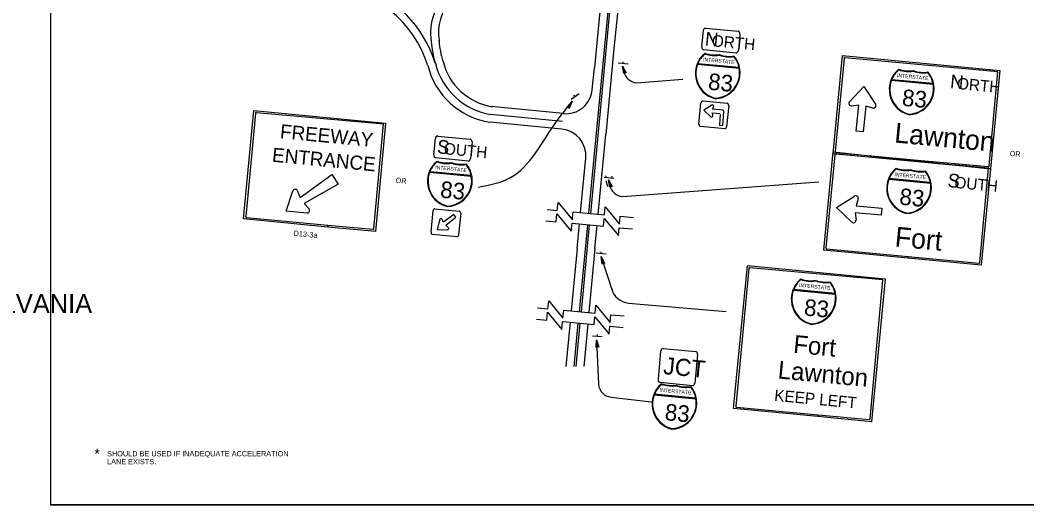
# Model space of a CAD drawing. Extents: x 644898 to 648326, y 298294 to 300670.
# Drawn here: x 647444 to 648015, y 299497 to 299772 of the extents above; entities that cross this region are included whole.
import ezdxf

# ---------------------------------------------------------------- set-up
doc = ezdxf.new("R2010")
doc.units = 0
doc.layers.add('1', color=7, linetype='Continuous')
doc.layers.add('2', color=7, linetype='Continuous')

msp = doc.modelspace()

# ---------------------------------------------------------------- linework, layer by layer
at = {"layer": '1'}
for p, q in [((647461.32, 300061.49), (647461.32, 299497.49)), ((648247.32, 299497.49), (647461.32, 299497.49)), ((647461.32, 299497.49), (648047.32, 299497.49))]:
    msp.add_line(p, q, dxfattribs=at)
at = {"layer": '2'}
for p, q in [((647802.82, 300046.87), (647766.22, 299662.87)), ((647803.95, 300046.87), (647767.34, 299662.77)), ((647797.95, 299920.74), (647780.45, 299754.37)), ((647779.95, 299854.24), (647769.7, 299745.49)), ((647830.52, 299757.24), (647831.4, 299766.55)), ((647832.61, 299767.9), (647851.13, 299766.13)), ((647681.57, 299760.62), (647681.57, 299760.99)), ((647852.11, 299764.53), (647851.27, 299755.24)), ((647780.51, 299754.34), (647776.07, 299707.49)), ((647849.9, 299753.74), (647831.52, 299755.49)), ((647683.82, 299748.87), (647683.82, 299749.24)), ((647785.84, 299747.69), (647785.97, 299748.81)), ((647832.3, 299753.28), (647832.3, 299753.28)), ((647840.43, 299752.53), (647840.43, 299752.53)), ((647848.68, 299751.78), (647848.68, 299751.78)), ((647904.91, 299696.59), (647910.29, 299752.34)), ((647911.16, 299750.72), (647906.16, 299697.97)), ((647910.29, 299752.34), (647999.41, 299743.84)), ((647768.4, 299732.94), (647769.59, 299745.42)), ((647788.72, 299747.44), (647783.09, 299747.94)), ((647828.05, 299747.41), (647851.68, 299745.16)), ((647851.68, 299745.53), (647828.3, 299747.66)), ((647942.22, 299744.16), (647942.22, 299744.16)), ((647950.47, 299743.41), (647950.47, 299743.41)), ((647993.41, 299689.72), (647998.23, 299743.18)), ((647999.41, 299743.84), (647994.16, 299688.09)), ((647793.39, 299736.93), (647819.79, 299738.9)), ((647938.09, 299738.29), (647961.59, 299736.04)), ((647961.59, 299736.41), (647938.22, 299738.66)), ((647958.59, 299742.66), (647958.59, 299742.66)), ((647914.22, 299726.17), (647922.43, 299734.75)), ((647922.43, 299734.75), (647928.99, 299724.68)), ((647760.97, 299730.71), (647756.43, 299727.37)), ((647758.65, 299729), (647758, 299729.92)), ((647828.91, 299713.3), (647830.01, 299725.58)), ((647831.06, 299726.61), (647844.9, 299725.29)), ((647570.67, 299659.64), (647576.6, 299721.19)), ((647576.6, 299721.18), (647651.25, 299714.07)), ((647751.99, 299719.44), (647711.07, 299723.49)), ((647836.26, 299724.2), (647831.69, 299721.31)), ((647831.69, 299721.31), (647835.6, 299717.61)), ((647836.65, 299721.85), (647837.25, 299723.64)), ((647842.34, 299721.42), (647836.65, 299721.85)), ((647836.7, 299718.14), (647836.66, 299719.92)), ((647836.66, 299719.92), (647840.75, 299719.55)), ((647842.44, 299712.7), (647843.06, 299720.43)), ((647845.74, 299724.12), (647844.49, 299711.87)), ((647919.44, 299724.14), (647915.29, 299723.69)), ((647918.04, 299709.46), (647919.44, 299724.14)), ((647923.42, 299723.7), (647922.02, 299709.03)), ((647927.57, 299722.56), (647923.42, 299723.7)), ((647577.48, 299719.56), (647571.93, 299661.07)), ((647751.2, 299710.6), (647710.32, 299714.49)), ((647751.59, 299714.94), (647710.7, 299718.99)), ((647840.98, 299719.18), (647840.54, 299712.85)), ((647644.67, 299654.16), (647650.07, 299713.41)), ((647651.25, 299714.07), (647645.45, 299652.52)), ((647843.58, 299710.81), (647829.75, 299712.13)), ((647840.54, 299712.85), (647842.44, 299712.7)), ((647922.02, 299709.03), (647918.04, 299709.46)), ((647678.64, 299696.02), (647679.52, 299705.34)), ((647680.73, 299706.69), (647699.25, 299704.91)), ((647700.23, 299703.31), (647699.39, 299694.02)), ((647771.79, 299662.34), (647776.07, 299707.49)), ((647899.64, 299641.9), (647905.02, 299697.65)), ((647905.01, 299697.64), (647994.16, 299688.09)), ((647906.54, 299697.34), (647952.81, 299693.05)), ((647698.02, 299692.52), (647679.64, 299694.27)), ((647680.42, 299692.06), (647680.42, 299692.06)), ((647688.55, 299691.31), (647688.55, 299691.31)), ((647761.77, 299663.3), (647764.71, 299694.24)), ((647905.89, 299696.02), (647900.89, 299643.27)), ((647952.71, 299692.04), (647904.91, 299696.59)), ((647952.71, 299692.04), (647952.81, 299693.05)), ((647952.81, 299693.05), (647952.71, 299692.04)), ((647994.16, 299688.09), (647952.71, 299692.04)), ((647952.81, 299693.05), (647992.79, 299689.34)), ((647676.17, 299686.19), (647699.8, 299683.94)), ((647699.8, 299684.31), (647676.42, 299686.44)), ((647696.8, 299690.56), (647696.8, 299690.56)), ((647940.74, 299688.05), (647940.74, 299688.05)), ((647948.99, 299687.3), (647948.99, 299687.3)), ((647957.12, 299686.55), (647957.12, 299686.55)), ((647988.14, 299635.02), (647992.95, 299688.48)), ((647994.16, 299688.09), (647988.89, 299633.4)), ((647602.88, 299671.76), (647620.73, 299684.82)), ((647620.73, 299684.82), (647624.29, 299679.32)), ((647780.61, 299682.61), (647775.11, 299683.11)), ((647776.16, 299681.4), (647777.03, 299678.15)), ((647776.23, 299682.99), (647776.23, 299684.11)), ((647779.61, 299682.74), (647779.73, 299683.86)), ((647785.48, 299672.43), (647896.94, 299680.75)), ((647936.62, 299682.18), (647960.12, 299679.93)), ((647960.12, 299680.3), (647936.74, 299682.55)), ((647594.82, 299664.14), (647598.66, 299675.53)), ((647601.2, 299675.73), (647602.88, 299671.76)), ((647624.29, 299679.32), (647605, 299668.37)), ((647906.92, 299666.11), (647916.99, 299672.66)), ((647919.11, 299671.25), (647917.97, 299667.09)), ((647606.64, 299663.02), (647594.82, 299664.14)), ((647605, 299668.37), (647607.93, 299665.39)), ((647677.03, 299652.08), (647678.13, 299664.37)), ((647679.18, 299665.39), (647693.02, 299664.07)), ((647693.86, 299662.9), (647692.61, 299650.66)), ((647742.75, 299665.11), (647748.6, 299664.55)), ((647757.56, 299663.7), (647775.35, 299662)), ((647915.5, 299657.9), (647906.92, 299666.11)), ((647932.2, 299661.72), (647917.53, 299663.11)), ((647917.53, 299663.11), (647917.97, 299658.96)), ((647917.97, 299667.09), (647932.64, 299665.69)), ((647932.64, 299665.69), (647932.2, 299661.72)), ((647618.47, 299655.08), (647570.67, 299659.64)), ((647572.33, 299660.42), (647618.57, 299656.09)), ((647681.99, 299659.46), (647680.42, 299653.73)), ((647684.11, 299657.84), (647683.17, 299659.59)), ((647690.02, 299662.25), (647684.11, 299657.84)), ((647685.39, 299656.14), (647691.15, 299660.6)), ((647691.15, 299660.6), (647690.02, 299662.25)), ((647742.13, 299658.64), (647747.98, 299658.08)), ((647756.94, 299657.23), (647774.73, 299655.53)), ((647784.31, 299661.15), (647791.78, 299660.44)), ((647618.47, 299655.08), (647618.57, 299656.09)), ((647618.57, 299656.09), (647618.47, 299655.08)), ((647645.45, 299652.52), (647618.47, 299655.08)), ((647618.57, 299656.09), (647644.08, 299653.81)), ((647680.42, 299653.73), (647686.4, 299653.55)), ((647686.92, 299654.7), (647685.39, 299656.14)), ((647759.82, 299642.87), (647761.15, 299656.83)), ((647765.61, 299656.4), (647760.91, 299607.08)), ((647766.72, 299656.29), (647762.02, 299606.98)), ((647769.95, 299642.87), (647771.18, 299655.87)), ((647783.69, 299654.68), (647791.16, 299653.97)), ((647691.7, 299649.59), (647677.87, 299650.91)), ((647759.82, 299642.87), (647756.45, 299607.51)), ((647769.95, 299642.87), (647766.48, 299606.55)), ((647776.27, 299639.67), (647770.65, 299640.17)), ((647773.4, 299639.92), (647773.52, 299641.04)), ((647947.44, 299637.34), (647899.64, 299641.9)), ((647901.27, 299642.65), (647947.53, 299638.36)), ((647780.02, 299618.37), (647773.95, 299636.83)), ((647947.44, 299637.34), (647947.53, 299638.36)), ((647947.53, 299638.36), (647947.44, 299637.34)), ((647988.89, 299633.4), (647947.44, 299637.34)), ((647947.53, 299638.36), (647987.52, 299634.65)), ((647848.56, 299552.09), (647856.36, 299633.24)), ((647857.23, 299631.61), (647849.82, 299553.5)), ((647856.36, 299633.23), (647934.37, 299625.79)), ((647886.68, 299625.22), (647886.68, 299625.22)), ((647894.93, 299624.47), (647894.93, 299624.47)), ((647903.05, 299623.72), (647903.05, 299623.72)), ((647925.89, 299546.33), (647933.18, 299625.13)), ((647934.37, 299625.79), (647926.7, 299544.65)), ((647882.55, 299619.34), (647906.05, 299617.09)), ((647906.05, 299617.47), (647882.68, 299619.72)), ((647788.94, 299611.92), (647844.31, 299607.18)), ((647737.43, 299609.32), (647743.28, 299608.76)), ((647752.24, 299607.91), (647770.03, 299606.21)), ((647736.81, 299602.85), (647742.66, 299602.29)), ((647751.62, 299601.44), (647769.42, 299599.74)), ((647755.83, 299601.04), (647753.45, 299575.99)), ((647760.29, 299600.61), (647757.95, 299575.99)), ((647761.41, 299600.51), (647759.07, 299575.99)), ((647765.87, 299600.08), (647763.57, 299575.99)), ((647778.99, 299605.36), (647786.46, 299604.65)), ((647778.38, 299598.89), (647785.84, 299598.18)), ((647774.07, 299592.74), (647768.45, 299593.24)), ((647770.82, 299591.12), (647771.99, 299565.97)), ((647771.2, 299592.99), (647771.32, 299594.12)), ((647805.87, 299568.6), (647807.37, 299584.85)), ((647808.62, 299586.22), (647827.12, 299584.47)), ((647828.12, 299582.85), (647826.62, 299566.6)), ((647825.24, 299565.1), (647806.87, 299566.85)), ((647807.74, 299565.85), (647807.74, 299565.85)), ((647827.12, 299558.1), (647803.74, 299560.22)), ((647815.87, 299565.1), (647815.87, 299565.1)), ((647824.12, 299564.35), (647824.12, 299564.35)), ((647778.99, 299558.6), (647801.99, 299555.97)), ((647803.49, 299559.97), (647827.12, 299557.72)), ((647896.36, 299547.54), (647848.56, 299552.09)), ((647850.19, 299552.84), (647896.46, 299548.55)), ((647896.36, 299547.54), (647896.46, 299548.55)), ((647896.46, 299548.55), (647896.36, 299547.54)), ((647926.7, 299544.65), (647896.36, 299547.54)), ((647896.46, 299548.55), (647925.36, 299545.91))]:
    msp.add_line(p, q, dxfattribs=at)
for points in [[(647998.23, 299743.18), (647911.66, 299751.09)], [(647786.34, 299742.39), (647786.57, 299742.54), (647785.47, 299746.31), (647786.34, 299742.39), (647786.24, 299742.12), (647785.47, 299746.31), (647787.05, 299742.73), (647787.31, 299742.63), (647785.47, 299746.31), (647787.58, 299742.54), (647787.31, 299742.63)], [(647754.42, 299723.32), (647754.69, 299723.25), (647757.09, 299726.53), (647754.42, 299723.32), (647754.17, 299723.27), (647757.09, 299726.53), (647755.13, 299722.95), (647755.3, 299722.73), (647757.09, 299726.53), (647755.38, 299722.37), (647755.3, 299722.73)], [(647650.06, 299713.41), (647577.98, 299719.94)], [(647992.95, 299688.48), (647906.39, 299696.4)], [(647778.42, 299677.89), (647778.65, 299678.04), (647777.56, 299681.81), (647778.42, 299677.89), (647778.33, 299677.63), (647777.56, 299681.81), (647779.13, 299678.23), (647779.4, 299678.14), (647777.56, 299681.81), (647779.66, 299678.04), (647779.4, 299678.14)], [(647748.6, 299664.55), (647749.02, 299669.03), (647757.13, 299659.22), (647757.26, 299660.6)], [(647757.26, 299660.6), (647757.56, 299663.7)], [(647775.35, 299662), (647775.78, 299666.48), (647783.88, 299656.67), (647784.31, 299661.15)], [(647747.98, 299658.08), (647748.41, 299662.56), (647756.51, 299652.75), (647756.94, 299657.23)], [(647774.73, 299655.53), (647775.16, 299660.01), (647783.27, 299650.2), (647783.69, 299654.68)], [(647774.17, 299634.35), (647774.4, 299634.49), (647773.47, 299638.3), (647774.17, 299634.35), (647774.06, 299634.09), (647773.47, 299638.3), (647774.89, 299634.66), (647775.15, 299634.55), (647773.47, 299638.3), (647775.41, 299634.45), (647775.15, 299634.55)], [(647933.17, 299625.13), (647857.73, 299631.99)], [(647743.28, 299608.76), (647743.71, 299613.24), (647751.81, 299603.43), (647752.24, 299607.91)], [(647742.66, 299602.29), (647743.09, 299606.77), (647751.19, 299596.96), (647751.62, 299601.44)], [(647770.03, 299606.21), (647770.46, 299610.69), (647778.57, 299600.88), (647778.99, 299605.36)], [(647769.42, 299599.74), (647769.84, 299604.22), (647777.95, 299594.41), (647778.38, 299598.89)], [(647770.93, 299586.99), (647771.16, 299587.26), (647770.82, 299591.12), (647770.93, 299586.99), (647770.69, 299586.73), (647770.82, 299591.12), (647771.54, 299587.28), (647771.79, 299587.17), (647770.82, 299591.12), (647772.06, 299586.93), (647771.79, 299587.17)]]:
    msp.add_lwpolyline(points, dxfattribs=at)
for centre, radius, start, end in [((647612.58, 299726.81), 65.66, 17.6452, 84.4929), ((647612.58, 299726.81), 70.14, 17.6452, 70.0659), ((647709.62, 299764.98), 32.86, 133.7836, 188.115), ((647709.62, 299764.98), 28.38, 90.5788, 188.115), ((647733.29, 299764.63), 56.37, 184.3638, 197.375), ((647733.29, 299764.63), 51.89, 184.3638, 197.375), ((647717.13, 299757.22), 34.31, 194.0499, 260.8471), ((647841.63, 299742.24), 14.78, 129.5662, 256.4361), ((647841.63, 299742.24), 14.47, 130.2586, 157.7735), ((647837.94, 299769.63), 16.98, 250.3162, 278.8163), ((647837.94, 299769.63), 17.29, 250.9067, 278.5552), ((647837.47, 299742.64), 14.78, 272.6963, 39.5662), ((647846.26, 299768.84), 17.29, 250.5773, 278.2258), ((647846.26, 299768.84), 16.98, 250.3162, 278.8163), ((647837.47, 299742.64), 14.47, 11.359, 38.8739), ((647911.6, 299750.64), 0.528, 84.2894, 175.6013), ((647717.13, 299757.22), 43.27, 194.0499, 260.8471), ((647717.13, 299757.22), 38.79, 194.0499, 260.8471), ((647794.08, 299744.9), 8, 192.9946, 265.0303), ((647841.63, 299742.24), 14.47, 159.0531, 256.4361), ((647837.47, 299742.64), 14.47, 272.6964, 10.0794), ((647951.54, 299733.16), 14.78, 129.5662, 256.4361), ((647951.54, 299733.16), 14.47, 130.2586, 157.7735), ((647947.85, 299760.55), 16.98, 250.3162, 278.8163), ((647947.85, 299760.55), 17.29, 250.9067, 278.5552), ((647947.38, 299733.56), 14.78, 272.6963, 39.5662), ((647956.17, 299759.76), 17.29, 250.5773, 278.2258), ((647956.17, 299759.76), 16.98, 250.3162, 278.8163), ((647997.72, 299742.54), 0.528, 354.144, 84.5077), ((647951.54, 299733.16), 14.47, 159.0531, 256.4361), ((647947.38, 299733.56), 14.47, 11.359, 38.8739), ((647753.47, 299734.36), 15, 264.3386, 354.5596), ((647947.38, 299733.56), 14.47, 272.6964, 10.0794), ((647915.25, 299725.17), 1.4, 134.486, 275.1515), ((647577.92, 299719.49), 0.528, 84.2894, 175.6013), ((647836.58, 299723.75), 0.628, 344.2746, 124.9401), ((647842.25, 299720.55), 0.84, 354.7992, 84.7992), ((647927.84, 299723.91), 1.4, 252.8745, 36.7811), ((647836.1, 299718.09), 0.628, 222.645, 6.5516), ((647749.78, 299695.67), 15, 354.5596, 84.5596), ((647906.61, 299697.9), 0.528, 174.0939, 265.2364), ((647689.75, 299681.02), 14.78, 129.5662, 256.4361), ((647689.75, 299681.02), 14.47, 130.2586, 157.7735), ((647686.06, 299708.41), 16.98, 250.3162, 278.8163), ((647686.06, 299708.41), 17.29, 250.9067, 278.5552), ((647694.38, 299707.62), 17.29, 250.5773, 278.2258), ((647694.38, 299707.62), 16.98, 250.3162, 278.8163), ((647906.33, 299695.95), 0.528, 84.2894, 175.6013), ((647689.75, 299681.02), 14.47, 159.0531, 256.4361), ((647685.59, 299681.42), 14.78, 272.6963, 39.5662), ((647685.59, 299681.42), 14.47, 11.359, 38.8739), ((647950.07, 299677.05), 14.78, 129.5662, 256.4361), ((647950.07, 299677.05), 14.47, 130.2586, 157.7735), ((647946.37, 299704.44), 16.98, 250.3162, 278.8163), ((647946.37, 299704.44), 17.29, 250.9067, 278.5552), ((647945.9, 299677.45), 14.78, 272.6963, 39.5662), ((647954.7, 299703.65), 17.29, 250.5773, 278.2258), ((647954.7, 299703.65), 16.98, 250.3162, 278.8163), ((647945.9, 299677.45), 14.47, 11.359, 38.8739), ((647992.44, 299687.85), 0.528, 354.144, 84.5077), ((647992.86, 299689.78), 0.528, 264.8056, 354.9575), ((647685.59, 299681.42), 14.47, 272.6964, 10.0794), ((647950.07, 299677.05), 14.47, 159.0531, 256.4361), ((647945.9, 299677.45), 14.47, 272.6964, 10.0794), ((647599.97, 299675.1), 1.4, 21.1732, 165.0799), ((647786.17, 299680.4), 8, 192.9946, 265.0303), ((647917.76, 299671.51), 1.4, 342.8745, 126.7811), ((647606.79, 299664.44), 1.4, 262.7848, 43.4503), ((647682.6, 299659.34), 0.625, 28.144, 164.5177), ((647916.5, 299658.92), 1.4, 224.486, 5.1515), ((647686.43, 299654.21), 0.625, 267.0622, 48.6931), ((647901.34, 299643.21), 0.528, 174.0939, 265.2364), ((647987.58, 299635.09), 0.528, 264.8056, 354.9575), ((647857.67, 299631.54), 0.528, 84.2894, 175.6013), ((647896, 299614.22), 14.78, 129.5662, 256.4361), ((647896, 299614.22), 14.47, 130.2586, 157.7735), ((647892.31, 299641.61), 16.98, 250.3162, 278.8163), ((647892.31, 299641.61), 17.29, 250.9067, 278.5552), ((647891.84, 299614.62), 14.78, 272.6963, 39.5662), ((647900.63, 299640.81), 17.29, 250.5773, 278.2258), ((647900.63, 299640.81), 16.98, 250.3162, 278.8163), ((647891.84, 299614.62), 14.47, 11.359, 38.8739), ((647789.88, 299622.63), 10.75, 192.9946, 264.9668), ((647896, 299614.22), 14.47, 159.0531, 256.4361), ((647891.84, 299614.62), 14.47, 272.6964, 10.0794), ((647779.95, 299566.54), 8, 184.4846, 263.4181), ((647817.07, 299554.81), 14.78, 129.5662, 256.4361), ((647817.07, 299554.81), 14.47, 130.2586, 157.7735), ((647813.38, 299582.2), 16.98, 250.3162, 278.8163), ((647813.38, 299582.2), 17.29, 250.9067, 278.5552), ((647812.91, 299555.21), 14.78, 272.6963, 39.5662), ((647821.7, 299581.4), 17.29, 250.5773, 278.2258), ((647821.7, 299581.4), 16.98, 250.3162, 278.8163), ((647812.91, 299555.21), 14.47, 11.359, 38.8739), ((647817.07, 299554.81), 14.47, 159.0531, 256.4361), ((647812.91, 299555.21), 14.47, 272.6964, 10.0794)]:
    msp.add_arc(centre, radius, start, end, dxfattribs=at)
for centre, major_axis, ratio, start_param, end_param in [((647832.51, 299766.42), (0.14, 1.52), 0.760552, 6.279242, 7.850039), ((647850.97, 299764.63), (0.14, 1.52), 0.767529, 4.711578, 6.282375), ((647831.63, 299757.11), (-0.15, -1.55), 0.769266, 4.712389, 6.283185), ((647850.06, 299755.36), (0.15, 1.55), 0.769266, 3.141593, 4.712389), ((647830.94, 299725.43), (-0.11, -1.16), 0.769266, 3.141593, 4.712389), ((647844.77, 299724.17), (0.11, 1.16), 0.769266, 4.712389, 6.283185), ((647649.56, 299712.77), (0, 0.528), 0.987556, 4.610182, 6.187326), ((647829.83, 299713.25), (-0.11, -1.16), 0.769266, 4.712389, 6.283185), ((647843.66, 299711.99), (0.11, 1.16), 0.769266, 3.141593, 4.712389), ((647680.63, 299705.2), (0.14, 1.52), 0.760552, 6.279242, 7.850039), ((647699.08, 299703.42), (0.14, 1.52), 0.767529, 4.711578, 6.282375), ((647679.75, 299695.9), (-0.15, -1.55), 0.769266, 4.712389, 6.283185), ((647698.18, 299694.14), (0.15, 1.55), 0.769266, 3.141593, 4.712389), ((647679.06, 299664.21), (-0.11, -1.16), 0.769266, 3.141593, 4.712389), ((647692.89, 299662.95), (0.11, 1.16), 0.769266, 4.712389, 6.283185), ((647572.41, 299661), (-0.556, 0), 0.992604, 6.180104, 7.77084), ((647644.15, 299654.22), (0, -0.496), 0.993424, 6.192525, 7.765974), ((647677.95, 299652.03), (-0.11, -1.16), 0.769266, 4.712389, 6.283185), ((647691.78, 299650.77), (0.11, 1.16), 0.769266, 3.141593, 4.712389), ((647932.67, 299624.5), (0, 0.527), 0.978402, 4.610182, 6.187326), ((647808.52, 299584.71), (-0.15, -1.55), 0.769266, 3.141593, 4.712389), ((647826.95, 299582.96), (0.15, 1.55), 0.769266, 4.712389, 6.283185), ((647806.97, 299568.48), (-0.15, -1.55), 0.769266, 4.712389, 6.283185), ((647825.41, 299566.72), (0.15, 1.55), 0.769266, 3.141593, 4.712389), ((647850.26, 299553.43), (0, 0.555), 0.945708, 1.467715, 3.058451), ((647925.42, 299546.39), (0, -0.57), 0.768686, 6.192525, 7.765974)]:
    msp.add_ellipse(centre, major_axis=major_axis, ratio=ratio, start_param=start_param, end_param=end_param, dxfattribs=at)
msp.add_spline([(647703.88, 299677.74), (647721.76, 299682.98), (647748.11, 299714.9), (647754.4, 299723.08), (647756.32, 299725.57)], degree=3, dxfattribs=at)

# ---------------------------------------------------------------- texts
at = {"layer": '1'}
msp.add_text('COMMONWEALTH OF PENNSYLVANIA', height=10.7828, dxfattribs=at).set_placement((647218.92, 299606.23))
at = {"layer": '2'}
for s, height, rotation, p in [('N', 7.75, 354.5817, (647832.06, 299758.14)), ('ORTH', 6.5, 354.5683, (647835.95, 299757.64)), ('INTERSTATE', 2.089, 354.5668, (647831.18, 299749.16)), ('83', 9.406, 354.5658, (647833.8, 299733.03)), ('INTERSTATE', 2.089, 354.5668, (647941.09, 299740.04)), ('N', 7.75, 354.5817, (647971.04, 299733.91)), ('ORTH', 6.5, 354.5683, (647974.93, 299733.41)), ('83', 9.406, 354.5658, (647943.72, 299723.91)), ('Lawnton', 11.25, 354.5683, (647939.37, 299703.1)), ('FREEWAY', 8, 354.5683, (647591.13, 299705.46)), ('S', 7.75, 354.5817, (647680.19, 299696.92)), ('OUTH', 6.5, 354.5683, (647684.07, 299696.42)), ('ENTRANCE', 8, 354.5683, (647586.64, 299692.16)), ('OR', 3, 354.4706, (648004.89, 299695.44)), ('INTERSTATE', 2.089, 354.5668, (647679.3, 299687.94)), ('INTERSTATE', 2.089, 354.5668, (647939.62, 299683.93)), ('OR', 3, 354.4706, (647656.83, 299680.18)), ('83', 9.406, 354.5658, (647681.92, 299671.81)), ('S', 7.75, 354.5817, (647969.58, 299677.8)), ('OUTH', 6.5, 354.5683, (647973.45, 299677.3)), ('83', 9.406, 354.5658, (647942.24, 299667.8)), ('D13-3a', 3, 354.4706, (647598.96, 299650.13)), ('Fort', 11.25, 354.5683, (647939.61, 299644.11)), ('INTERSTATE', 2.089, 354.5668, (647885.55, 299621.09)), ('83', 9.406, 354.5658, (647888.18, 299604.97)), ('Fort', 10.125, 354.5701, (647882.08, 299583.8)), ('JCT', 9.706, 354.5666, (647808.37, 299571.72)), ('Lawnton', 10.125, 354.5701, (647873.29, 299569.23)), ('INTERSTATE', 2.089, 354.5668, (647806.62, 299561.72)), ('KEEP LEFT', 6.493, 354.5683, (647871.37, 299556.54)), ('83', 9.406, 354.5658, (647809.24, 299545.6))]:
    msp.add_text(s, height=height, rotation=rotation, dxfattribs=at).set_placement(p)
for s, height, p in [('*', 5.85, (647486.19, 299523.48)), ('SHOULD BE USED IF INADEQUATE ACCELERATION', 3, (647493.35, 299525.02)), ('LANE EXISTS.', 3, (647493.35, 299520.52))]:
    msp.add_text(s, height=height, dxfattribs=at).set_placement(p)

doc.saveas('drawing.dxf')
